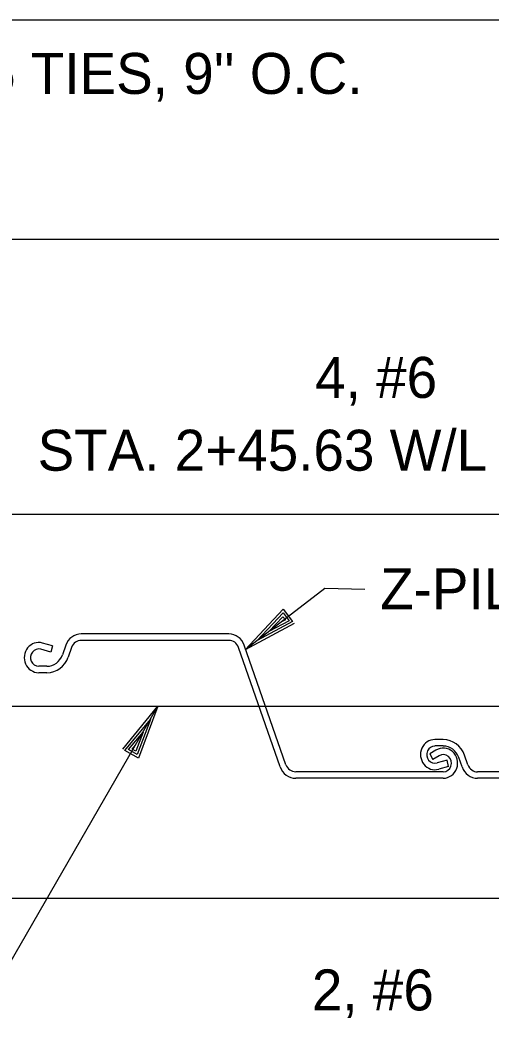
# Model space of a CAD drawing. Extents: x 22369.6 to 22428.3, y 22369.6 to 22415.
# Drawn here: x 22413.201 to 22415.345, y 22397.942 to 22402.487 of the extents above; entities that cross this region are included whole.
import ezdxf

# ---------------------------------------------------------------- set-up
doc = ezdxf.new("R2010")
doc.units = 0
for name, color, linetype in [('Level 1', 7, 'Continuous'), ('Level 2', 7, 'Continuous'), ('Level 38', 7, 'Continuous'), ('Level 4', 7, 'Continuous')]:
    doc.layers.add(name, color=color, linetype=linetype)

msp = doc.modelspace()

# ---------------------------------------------------------------- linework, layer by layer
at = {"layer": 'Level 1'}
for p, q in [((22411.3438, 22402.4874), (22417.4816, 22402.4874)), ((22416.2926, 22401.4874), (22411.9708, 22401.4874)), ((22412.7261, 22400.2375), (22417.5249, 22400.2375)), ((22414.5894, 22399.8977), (22414.226, 22399.6197)), ((22414.7711, 22399.8942), (22414.5894, 22399.8977)), ((22411.3296, 22399.3625), (22417.6401, 22399.3625)), ((22412.6691, 22398.4876), (22415.6754, 22398.4876))]:
    msp.add_line(p, q, dxfattribs=at)
msp.add_lwpolyline([(22412.8255, 22398.0443), (22413.0683, 22398.0443), (22413.8291, 22399.3625)], dxfattribs=at)
at = {"layer": 'Level 2'}
for p, q in [((22414.1517, 22399.6916), (22413.4802, 22399.6916)), ((22413.3484, 22399.6373), (22413.303, 22399.65)), ((22413.3484, 22399.6373), (22413.3411, 22399.6089)), ((22413.4095, 22399.64), (22413.3942, 22399.5961)), ((22413.436, 22399.6299), (22413.4207, 22399.586)), ((22414.1516, 22399.6622), (22413.4802, 22399.6622)), ((22414.3855, 22399.0859), (22414.1958, 22399.6299)), ((22414.412, 22399.096), (22414.2223, 22399.64)), ((22414.2811, 22399.6618), (22414.2811, 22399.6618)), ((22413.3411, 22399.6089), (22413.2957, 22399.6216)), ((22414.226, 22399.6197), (22414.226, 22399.6197)), ((22413.3236, 22399.5444), (22413.286, 22399.5444)), ((22413.3236, 22399.515), (22413.286, 22399.515)), ((22413.3236, 22399.363), (22413.3236, 22399.363)), ((22413.8291, 22399.3625), (22413.8291, 22399.3625)), ((22415.1277, 22399.363), (22415.1277, 22399.363)), ((22415.1277, 22399.3625), (22415.1277, 22399.3625)), ((22413.7944, 22399.3025), (22413.7944, 22399.3025)), ((22415.1277, 22399.2104), (22415.0901, 22399.2104)), ((22415.1277, 22399.1811), (22415.0901, 22399.1811)), ((22415.0948, 22399.1625), (22415.0663, 22399.1453)), ((22415.0663, 22399.1453), (22415.0804, 22399.1198)), ((22415.1089, 22399.137), (22415.0804, 22399.1198)), ((22415.2136, 22399.0855), (22415.1983, 22399.1294)), ((22415.2401, 22399.0956), (22415.2248, 22399.1394)), ((22415.1452, 22399.1166), (22415.0998, 22399.1039)), ((22415.1525, 22399.0881), (22415.1071, 22399.0754)), ((22415.1525, 22399.0881), (22415.1452, 22399.1166)), ((22415.1277, 22399.0637), (22414.4562, 22399.0637)), ((22415.9557, 22399.0633), (22415.2843, 22399.0633)), ((22415.1277, 22399.0343), (22414.4562, 22399.0343)), ((22415.9558, 22399.0339), (22415.2843, 22399.0339))]:
    msp.add_line(p, q, dxfattribs=at)
for points in [[(22414.4492, 22399.7384), (22414.226, 22399.6197), (22414.3989, 22399.804), (22414.4419, 22399.7479), (22414.2811, 22399.6618), (22414.3986, 22399.7869), (22414.4261, 22399.7509), (22414.3341, 22399.7023), (22414.3982, 22399.7699), (22414.4095, 22399.7551), (22414.3891, 22399.7445)], [(22413.6686, 22399.1672), (22413.8291, 22399.3625), (22413.7402, 22399.1259), (22413.679, 22399.1612), (22413.7944, 22399.3025), (22413.734, 22399.1418), (22413.6948, 22399.1645), (22413.7611, 22399.2447), (22413.7278, 22399.1577), (22413.7116, 22399.1671), (22413.7264, 22399.1847)]]:
    msp.add_lwpolyline(points, dxfattribs=at)
for centre, major_axis, start_param, end_param in [((22413.4802, 22399.6131), (0, 0.0785), 0, 1.221657), ((22414.1516, 22399.6131), (0, 0.0785), 5.061636, 6.283185), ((22413.286, 22399.5837), (0, 0.0687), 6.021386, 9.424778), ((22413.4802, 22399.6131), (0, 0.0491), 0, 1.221657), ((22414.1516, 22399.6131), (0, 0.0491), 5.061636, 6.283185), ((22413.286, 22399.5837), (0, 0.0392), 6.021386, 9.424778), ((22413.3236, 22399.6229), (0, 0.0785), 3.141593, 4.36325), ((22413.3236, 22399.6229), (0, 0.1079), 3.141593, 4.36325), ((22415.0901, 22399.1418), (0, -0.0687), 3.141593, 6.544985), ((22415.0901, 22399.1418), (0, -0.0392), 3.141593, 6.544985), ((22415.1277, 22399.103), (0, 0.0687), 3.141593, 6.806784), ((22415.1277, 22399.1025), (0, -0.1079), 1.919936, 3.141593), ((22415.1277, 22399.1025), (0, -0.0785), 1.919936, 3.141593), ((22415.1277, 22399.103), (0, 0.0392), 3.141593, 6.806784), ((22414.4562, 22399.1128), (0, 0.0785), 1.920043, 3.141593), ((22414.4562, 22399.1128), (0, 0.0491), 1.920043, 3.141593), ((22415.2843, 22399.1124), (0, -0.0785), 5.061528, 6.283185), ((22415.2843, 22399.1124), (0, -0.0491), 5.061528, 6.283185)]:
    msp.add_ellipse(centre, major_axis=major_axis, ratio=0.957796, start_param=start_param, end_param=end_param, dxfattribs=at)
at = {"layer": 'Level 38'}
msp.add_line((22415.1277, 22399.3625), (22415.1277, 22399.3625), dxfattribs=at)

# ---------------------------------------------------------------- texts
at = {"layer": 'Level 4'}
for s, height, p in [("#5 TIES, 9'' O.C.", 0.186667, (22412.9034, 22402.1506)), ('4, #6', 0.18667, (22414.5449, 22400.7663)), ('STA. 2+45.63 W/L', 0.186667, (22413.2813, 22400.4347)), ('Z-PILES', 0.18667, (22414.8406, 22399.8039)), ('2, #6', 0.18667, (22414.53, 22397.9769))]:
    msp.add_text(s, height=height, dxfattribs=at).set_placement(p)

doc.saveas('drawing.dxf')
